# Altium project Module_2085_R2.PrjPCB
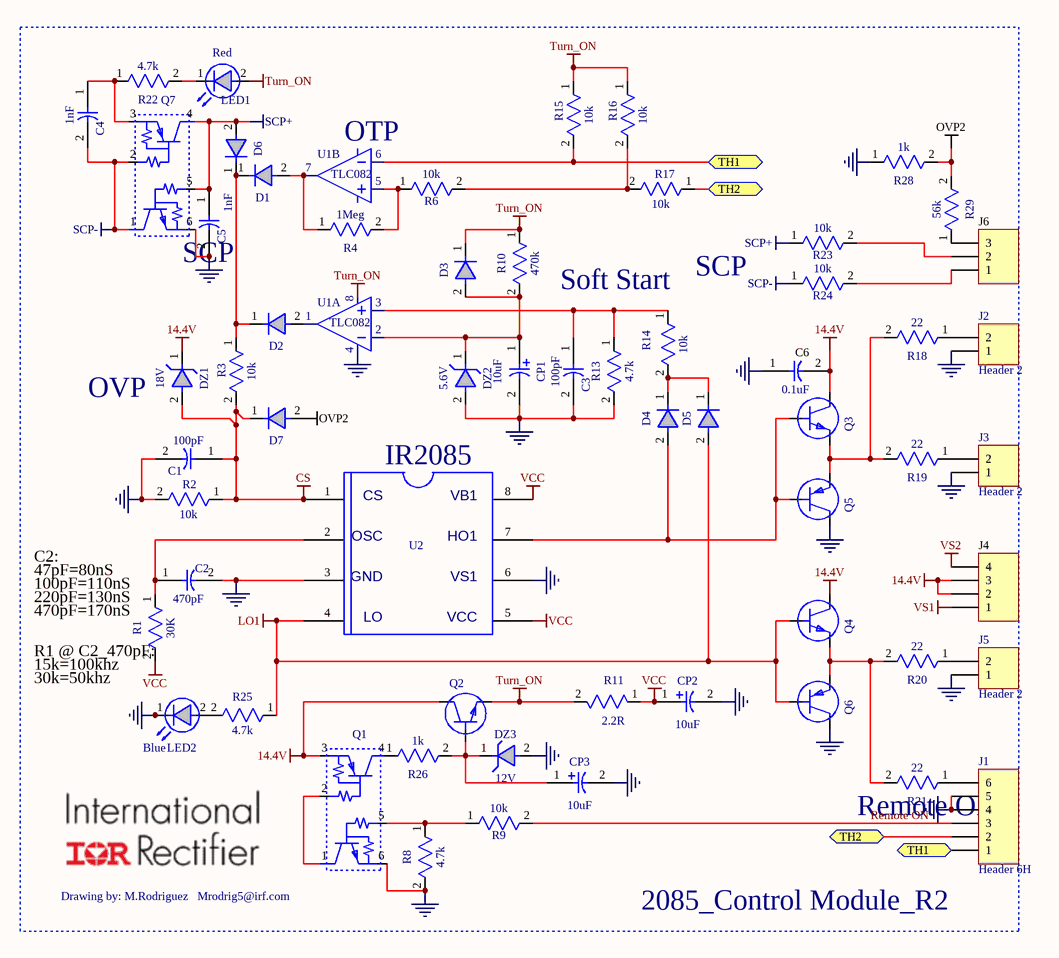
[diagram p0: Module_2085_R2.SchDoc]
1 sheet, 61 parts. Net scope: flat (ports and power ports of the same name join across sheets).
Board file: Module_2085_R2.PcbDoc

## Sheet Module_2085_R2.SchDoc
size Letter; SheetNumber: 0; SheetTotal: 0; PageSetup: Record=PageOptions|CenterHorizontal=True|CenterVertical=True|PrintScale=0.95|XCorrection=1.00|YCorrection=1.00|PrintKind=1|BorderSize=5000000|LeftOffset=0|BottomOffset=0|Orientation=2|PaperLength=1000|PaperWidth=1000|Scale=100|PaperSource=15|PrintQuality=600|MediaType=1|DitherType=10|PaperKind=Letter|PrintScaleMode=1

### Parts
C1  value 100pF  [C-603]  (hidden comment: C-603)
C2  value 470pF  [C-603]  (hidden comment: C-603)
C3  value 100pF  [C-603]  (hidden comment: C-603)
C4  value 1nF  [C-603]  (hidden comment: C-603)
C5  value 1nF  [C-603]  (hidden comment: C-603)
C6  value 0.1uF  [C-805]  (hidden comment: C-805)
CP1  value 10uF  [C-TAN-a]  (hidden comment: C-TAN-A)
CP2  value 10uF  [C-TAN-a]  (hidden comment: C-TAN-A)
CP3  value 10uF  [C-TAN-a]  (hidden comment: C-TAN-A)
D1  SOD323_D  [SOD523_D]  (value not drawn)
D2  SOD323_D  [SOD523_D]  (value not drawn)
D3  SOD323_D  [SOD523_D]  (value not drawn)
D4  SOD323_D  [SOD523_D]  (value not drawn)
D5  SOD323_D  [SOD523_D]  (value not drawn)
D6  SOD323_D  [SOD523_D]  (value not drawn)
D7  SOD323_D  [SOD523_D]  (value not drawn)
DZ1  value 18V  [SOD323_Z]  (hidden comment: SOD123_Z)
DZ2  value 5.6V  [SOD323_Z]  (hidden comment: SOD123_Z)
DZ3  value 12V  [SOD323_Z]  (hidden comment: SOD123_Z)
J1  Header 6H  [HDR1X6H]
J2  Header 2  [HDR1X2H]
J3  Header 2  [HDR1X2H]
J4  Header 4H  [HDR1X4H]  (value not drawn)
J5  Header 2  [HDR1X2H]
J6  Header 3H  [HDR1X3H]  (value not drawn)
LED1  value Red  [LED-805]  (hidden comment: LED-805)
LED2  value Blue  [LED-805]  (hidden comment: LED-805)
Q1  XN4311  [XN04311_XN04311(Primary)]  (value not drawn)
Q2  PBSS305NX  [SOT89]  (value not drawn)
Q3  PBSS305NX  [SOT89]  (value not drawn)
Q4  PBSS305NX  [SOT89]  (value not drawn)
Q5  PBSS305PX  [SOT89]  (value not drawn)
Q6  PBSS305PX  [SOT89]  (value not drawn)
Q7  XN4311  [XN04311_XN04311(Primary)]  (value not drawn)
R1  value 30K  [R-603]  (hidden comment: R-603)
R2  value 10k  [R-603]  (hidden comment: R-603)
R3  value 10k  [R-603]  (hidden comment: R-603)
R4  value 1Meg  [R-603]  (hidden comment: R-603)
R6  value 10k  [R-603]  (hidden comment: R-603)
R8  value 4.7k  [R-603]  (hidden comment: R-603)
R9  value 10k  [R-603]  (hidden comment: R-603)
R10  value 470k  [R-603]  (hidden comment: R-603)
R11  value 2.2R  [R-1206]  (hidden comment: R-1206)
R13  value 4.7k  [R-603]  (hidden comment: R-603)
R14  value 10k  [R-603]  (hidden comment: R-603)
R15  value 10k  [R-603]  (hidden comment: R-603)
R16  value 10k  [R-603]  (hidden comment: R-603)
R17  value 10k  [R-603]  (hidden comment: R-603)
R18  value 22  [R-805]  (hidden comment: R-805)
R19  value 22  [R-805]  (hidden comment: R-805)
R20  value 22  [R-805]  (hidden comment: R-805)
R21  value 22  [R-805]  (hidden comment: R-805)
R22  value 4.7k  [R-603]  (hidden comment: R-603)
R23  value 10k  [R-603]  (hidden comment: R-603)
R24  value 10k  [R-603]  (hidden comment: R-603)
R25  value 4.7k  [R-603]  (hidden comment: R-603)
R26  value 1k  [R-603]  (hidden comment: R-603)
R28  value 1k  [R-603]  (hidden comment: R-603)
R29  value 56k  [R-603]  (hidden comment: R-603)
U1  TLC082  [SO8]  (parts A,B of 2)
U2  IR2086  [SO8]  (value not drawn)

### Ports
TH1, TH2

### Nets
14.4V: C6.2 DZ1.1 J4.2 J4.3 Q1.3(E1) Q2.2 Q3.2 Q4.2
CS: C1.1 D7.1 DZ1.2 R2.1 R3.2 U2.1
GND: C1.2 C2.2 C3.2 C5.2 C6.1 CP1.2 CP2.2 CP3.2 DZ2.2 DZ3.2 J1.4 J1.5 J2.1 J3.1 J5.1 LED2.1(K) Q1.6(E2) Q5.2 Q6.2 Q7.6(E2) R2.2 R8.2 R13.2 R28.1 U1.4 U2.3 U2.6
LO1: D5.2 Q4.1 Q6.1 R25.1 U2.4
OVP2: D7.2 R28.2 R29.2
SCP+: C5.1 D6.2 Q7.4(C1) Q7.5(B2) R23.1
SCP-: C4.2 Q7.1(C2) Q7.2(B1) R24.1
Turn_ON: D3.1 LED1.2(A) Q2.3 R10.1 R11.2 R15.1 R16.1 U1.8
VCC: CP2.1 R1.2 R11.1 U2.5 U2.8
VS1: J4.1
VS2: J4.4
Remote ON: J1.3 R9.2
NetC2_1: C2.1 R1.1 U2.2
NetC3_1: C3.1 R13.1 R14.1 U1.3
NetC4_1: C4.1 Q7.3(E1) R22.1
NetCP1_1: CP1.1 D3.2 DZ2.1 R10.2 U1.2
NetCP3_1: CP3.1 DZ3.1 Q2.1 R26.2
NetD1_1: D1.1 D2.1 D6.1 R3.1
NetD1_2: D1.2 R4.1 U1.7
NetD2_2: D2.2 U1.1
NetD4_1: D4.1 D5.1 R14.2
NetD4_2: D4.2 Q3.1 Q5.1 U2.7
NetJ1_1: J1.1 R15.2 U1.6 ; port TH1
NetJ1_2: J1.2 R17.1 ; port TH2
NetJ1_6: J1.6 R21.1
NetJ2_2: J2.2 R18.1
NetJ3_2: J3.2 R19.1
NetJ5_2: J5.2 R20.1
NetJ6_1: J6.1 R24.2
NetJ6_2: J6.2 R23.2
NetJ6_3: J6.3 R29.1
NetLED1_1: LED1.1(K) R22.2
NetLED2_2: LED2.2(A) R25.2
NetQ1_1: Q1.1(C2) Q1.2(B1)
NetQ1_5: Q1.5(B2) R8.1 R9.1
NetQ3_3: Q3.3 Q5.3 R18.2 R19.2
NetQ4_3: Q4.3 Q6.3 R20.2 R21.2
NetR4_2: R4.2 R6.1 U1.5
NetR6_2: R6.2 R16.2 R17.2

Not connected (* = marked no-connect by the designer): Q1 4(C1); Q2 4; Q3 4; Q4 4; Q5 4; Q6 4; R26 1

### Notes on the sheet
- (near U1) OTP
- (near Q7) SCP
- Soft Start
- SCP
- OVP
- (near U2) IR2085
- C2:
- (near R1) 100pF=110nS
- 47pF=80nS
- (near R1) 470pF=170nS
- (near R1) R1 @ C2_470pF:
- (near R1) 220pF=130nS
- (near R1) 15k=100khz
- 30k=50khz
- (near R21) Remote ON
- (near Q1) Drawing by: M.Rodriguez   Mrodrig5@irf.com
- (near J1) 2085_Control Module_R2

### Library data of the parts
C1 C3 = C-603: CAP CERAMIC 100PF 50V NP0 0603; Vendor: Yageo; Cost 1000: 0.01456
C2 = C-603: CAP CER 470PF 50V 5% C0G 0603; Vendor: Murata North America
C4 C5 = C-603: CAP CERAMIC 1000PF 50V NPO 0603; Vendor: Kemet; Cost 1000: 0.01404
C6 = C-805: CAP CERM .10UF 50V 20% 0805 SMD; Vendor: AVX Corporation; Cost 1000: 0.01875
CP1-CP3 = C-TAN-B: CAP TANTALUM 10UF 16V 10% SMD; Vendor: Kemet
D1-D3 D6 D7 = SOD323_D: DIODE SWITCH 100V 150MW SOD-523; Value: 1N4148WT-7; Vendor: Diodes Inc
D4 D5 = SOD323_D: Value: 1N4148WT-7; Description: DIODE SWITCH 100V 150MW SOD-523; Vendor: Diodes Inc
DZ1 = SOD123_Z: Description: DIODE ZENER 200MW 18V SOD323; Vendor: Diodes Inc
DZ2 = SOD123_Z: DIODE ZENER 5.6V 200MW SOD-323; Vendor: Rohm
DZ3 = SOD123_Z: DIODE ZENER 200MW 12V SOD323; Vendor: Diodes Inc
J1 = Header 6H: Header, 6-Pin, Right Angle; Vendor: 3M; Cost 1000: 0.38000
J2 J3 J5 = Header 2: Header, 2-Pin; Vendor: 3M
J4 = Header 4H: Header, 4-Pin, Right Angle; Vendor: 3M
J6 = Header 3H: Header, 3-Pin, Right Angle; Vendor: 3M
LED1 = LED-805: LED RED ORAN CLEAR THIN 0805 SMD; Vendor: Lite-On Inc; Cost 1000: 0.07000
LED2 = LED-805: LED 468NM BLUE CLEAR 0805 SMD; Vendor: Lite-On Inc; Cost 1000: 0.20000
Q1 Q7 = XN4311: TRANS ARRAY PNP/NPN W/RES MINI6P; Value: XN04311; Vendor: Panasonic - SSG
Q2-Q4 = SOT89-NPN: TRANS NPN 80V 4.6A SOT-89; Vendor: NXP Semiconductors
Q5 Q6 = SOT89-PNP: TRANS PNP 80V 4A SOT-89; Vendor: NXP Semiconductors
R1 = R-603: RES 30K OHM 1/8W 5% 0805 SMD; Vendor: Rohm; Cost 1000: 0.01595
R2 R3 R6 R9 R14-R17 R23 R24 = R-603: RES 10K OHM 1/10W 5% 0603 SMD; Vendor: Rohm; Cost 1000: 0.01462
R4 = R-603: RES 1.0M OHM 1/10W 5% 0603 SMD; Vendor: Yageo; Cost 1000: 0.01479
R8 R13 R22 R25 = R-603: RES 4.7K OHM 1/10W 5% 0603 SMD; Cost 1000: 0.01462; Vendor: Rohm
R10 = R-603: RES 470K OHM 1/10W 5% 0603 SMD; Vendor: Rohm; Cost 1000: 0.01462
R11 = R-1206: RES 2.2 OHM 1/4W 1% 1206 SMD; Vendor: Panasonic - ECG; Cost 1000: 0.13050
R18-R21 = R-805: RES 22 OHM 1/8W 5% 0805 SMD; Vendor: Rohm; Cost 1000: 0.01595
R26 R28 = R-603: RES 1.0K OHM 1/10W 5% 0603 SMD; Vendor: Rohm; Cost 1000: 0.01462
R29 = R-603: RES 56K OHM 1/10W 5% 0603 SMD; Vendor: Rohm; Cost 1000: 0.01462
U1 = LM833: IC DUAL HI-OUTSEL OP AMP 8-SOIC; Value: TLC082IDR; Vendor: Texas Instruments
U2 = IR2085: Controller and Gate Driver; Value: IR2085; Vendor: International Rectifier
